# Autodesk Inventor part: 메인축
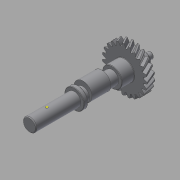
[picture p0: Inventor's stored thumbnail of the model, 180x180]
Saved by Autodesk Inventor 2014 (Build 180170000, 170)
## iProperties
Created: 2016-12
Part Number: 메인축
Material: 강철, 탄소
Document SubType Name: Modeling
Designer: mduedu
Categories: <?xml version="1.0" encoding="UTF-16"?> <MemberInstance><Categories><FamilyTemplate><FamilyTemplateParameter ValueType="xs:double" Id="1" ObjectReferenceKey="da
Density: 7.87 g/cm^3
Appearance: 기본값
Mass: 491.06 g
Surface Area: 169.938 cm^2
Volume: 62.3964 cm^3
CustomPartVersion: 1
Author: mduedu
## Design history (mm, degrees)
sketch "Sketch1"
  geometry: C1 r 28.558 at (0, 0)
  constraints: 1 centre point
  dimensions: "d0" = 57.11622 diameter of C1 (= da_da)
extrude "Extrusion1" new body sketch "Sketch1" distance "d1" = 10 (= da_b); taper "d2" = 0 deg
workplane "Work Plane2"
sketch "Sketch2"
  geometry: C1 r 28.558 at (0, 0) reference; C2 r 26.558 at (0, 0)
  constraints: 1 centre point, 1 coincident
  dimensions: "d3" = 53.11622 diameter of C2 (= da_dw)
feature "피치 지름" sketch "Sketch2" dims "d4" = 10, "d5" = 0
workplane "Work Plane8"
workplane "Work Plane9"
feature "스퍼 기어" dims "da_b" = 10, "da_d" = 53.11622, "da_aw" = 43.87862, "da_da" = 57.11622, "da_df" = 48.11622, "da_dw" = 53.11622, angle "da_beta" = 30 deg, "da_lefttooth" = 10, "da_righttooth" = 0
sketch "스케치3"
  geometry: C1 r 12.5 at (0, 0); 1 further point
  constraints: 1 centre point, 1 coincident
  dimensions: "d49" = 25 diameter of C1
extrude "돌출2" join sketch "스케치3" distance "d50" = 16; taper "d51" = 0 deg
sketch "스케치4"
  geometry: C1 r 8.5 at (0, 0); 1 further point
  constraints: 1 centre point, 1 coincident
  dimensions: "d52" = 17 diameter of C1
extrude "돌출3" join sketch "스케치4" distance "d53" = 105; taper "d54" = 0 deg
sketch "스케치5"
  geometry: C1 r 7.5 at (0, 0); 1 further point
  constraints: 1 centre point, 1 coincident
  dimensions: "d55" = 15 diameter of C1
extrude "돌출4" join sketch "스케치5" distance "d56" = 16; taper "d57" = 0 deg
sketch "스케치6"
  geometry: C1 r 4 at (0, 0); 1 further point
  constraints: 1 centre point, 1 coincident
  dimensions: "d58" = 8 diameter of C1
extrude "돌출5" join sketch "스케치6" distance "d59" = 7; taper "d60" = 0 deg
chamfer "모따기1" distance "d61" = 0.5; stored, may be unused: second distance "d62" = 2, angle "d63" = 45 deg
fillet "모깎기1" dims "d64" = 0.5
node "작업 평면11"
sketch "스케치7"
  geometry: C1 r 11.5 at (0, 3); C2 r 8.5 at (0, 0) reference; 1 further point
  constraints: 1 centre point, 1 tangent, 1 vertical alignment
  dimensions: "d66" = 3 distance of point (0, 0) C1.centre; "d67" = 23 diameter of C1 (derived)
extrude "돌출6" join sketch "스케치7" stored distance "d68" = 24; taper "d69" = 0 deg
node "작업 평면12"
sketch "스케치8"
  geometry: C1 r 12.5 at (0, 0) reference; 1 further point
extrude "돌출7" join sketch "스케치8" distance "d71" = 5; taper "d72" = 0 deg
chamfer "모따기2" distance "d73" = 0.5; stored, may be unused: second distance "d74" = 2, angle "d75" = 45 deg
chamfer "모따기3" distance "d76" = 1; stored, may be unused: second distance "d77" = 2, angle "d78" = 45 deg
node "작업 평면13"
sketch "스케치9" dims "d81" = 18
  geometry: L1 (2.5, 95.5)-(-2.5, 95.5); L2 (-2.5, 95.5)-(-2.5, 82.5); L3 (-2.5, 82.5)-(2.5, 82.5); L4 (2.5, 82.5)-(2.5, 95.5); L5 (-7.5, 105)-(7.5, 105) reference; 3 further points
  constraints: 8 end point, 2 horizontal alignment, 2 midpoint, 2 parallel, 1 horizontal, 1 perpendicular, 1 vertical alignment, 4 other
  dimensions: "d79" = 5 distance between parallel lines of L2 L4; "d82" = 7 dimension on L5
extrude "돌출8" cut sketch "스케치9" distance "d83" = 3; taper "d84" = 0 deg
sketch "스케치10"
  geometry: L1 (-8.5, 74)-(-8.5, 130) reference; L2 (8.5, 74)-(8.5, 130) reference; L3 (8.5, 109)-(-8.5, 109); L4 (-7.5, 131)-(7.5, 131) reference; L5 (8.5, 109)-(7, 109); L6 (7, 109)-(8.5, 107.5); L7 (8.5, 107.5)-(8.5, 109); 1 further point
  constraints: 8 end point, 4 point on line, 2 perpendicular
  dimensions: "d85" = 22 distance between parallel lines of L3 L4; "d86" = 45 deg angle of L6 L5; "d87" = 3 diameter of L6.end L3
revolve "회전1" stored, may be unused: angle "d88" = 90 deg
node "작업점1"
body "Solid1"
body "Srf1"
other parameters: "d16" = 43.87862 (= da_aw), "d17" = 0, "d34" = 1.36591 (computed from da_z), "d39" = 0, "d41" = 0, "d43" = 43.87862 (= da_aw), "d46" = 43.87862 (= da_aw), "d47" = 0, "d48" = 0, "d65" = 25, "d70" = 48
